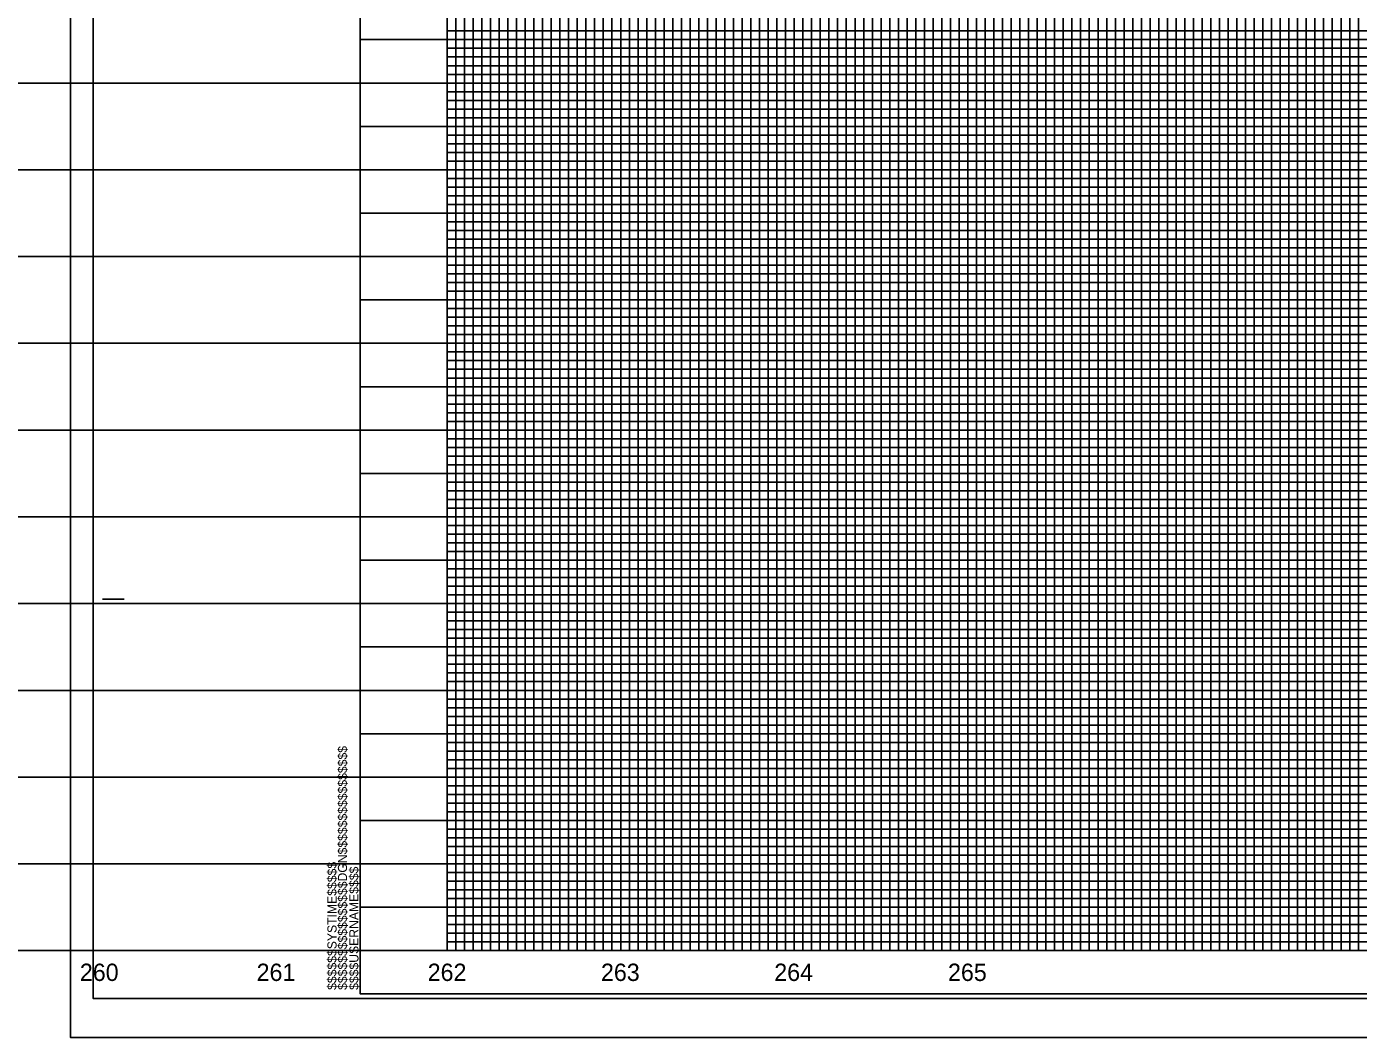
# Model space of a CAD drawing. Extents: x 2345490 to 2445302, y 465165 to 573888.
# Drawn here: x 2406279 to 2407047, y 564227 to 564809 of the extents above; entities that cross this region are included whole.
import ezdxf

# ---------------------------------------------------------------- set-up
doc = ezdxf.new("R2010")
doc.units = 0
for name, color, linetype in [('Old_Level_18', 7, 'Continuous'), ('Old_Level_40', 7, 'Continuous'), ('Old_Level_41', 7, 'Continuous'), ('Old_Level_42', 7, 'Continuous'), ('Old_Level_43', 7, 'Continuous'), ('Old_Level_50', 7, 'Continuous'), ('Old_Level_51', 7, 'Continuous'), ('Old_Level_52', 7, 'Continuous'), ('Old_Level_57', 7, 'Continuous'), ('Old_Level_62', 7, 'Continuous'), ('Old_Level_63', 7, 'Continuous')]:
    doc.layers.add(name, color=color, linetype=linetype)

msp = doc.modelspace()

# ---------------------------------------------------------------- linework, layer by layer
at = {"layer": 'Old_Level_18'}
msp.add_line((2406471.5425, 564251.534), (2406471.5425, 564251.534), dxfattribs=at)
msp.add_line((2406471.5425, 564251.534), (2406471.5425, 564251.534), dxfattribs=at)
msp.add_lwpolyline([(2407971.5425, 565301.534), (2406471.5425, 565301.534), (2406471.5425, 564251.534), (2407971.5425, 564251.534)], close=True, dxfattribs=at)
at = {"layer": 'Old_Level_40'}
msp.add_line((2406471.5425, 564251.534), (2406471.5425, 564251.534), dxfattribs=at)
msp.add_line((2406471.5425, 564251.534), (2406471.5425, 564251.534), dxfattribs=at)
msp.add_line((2406471.5425, 564251.534), (2406471.5425, 564251.534), dxfattribs=at)
msp.add_line((2406471.5425, 564251.534), (2406471.5425, 564251.534), dxfattribs=at)
at = {"layer": 'Old_Level_41'}
for p, q in [((2406323.0425, 564479.034), (2406335.5425, 564479.034)), ((2407971.5425, 564276.534), (2406471.5425, 564276.534))]:
    msp.add_line(p, q, dxfattribs=at)
for points in [[(2406471.5425, 565301.534), (2406521.5425, 565301.534), (2406521.5425, 564276.534), (2406571.5425, 564276.534), (2406571.5425, 565301.534), (2406621.5425, 565301.534), (2406621.5425, 564276.534), (2406671.5425, 564276.534), (2406671.5425, 565301.534), (2406721.5425, 565301.534), (2406721.5425, 564276.534), (2406771.5425, 564276.534), (2406771.5425, 565301.534), (2406821.5425, 565301.534), (2406821.5425, 564276.534), (2406871.5425, 564276.534), (2406871.5425, 565301.534), (2406921.5425, 565301.534), (2406921.5425, 564276.534), (2406971.5425, 564276.534), (2406971.5425, 565301.534), (2407021.5425, 565301.534), (2407021.5425, 564276.534), (2407071.5425, 564276.534)], [(2406546.5425, 564276.534), (2406546.5425, 565301.534), (2406596.5425, 565301.534), (2406596.5425, 564276.534), (2406646.5425, 564276.534), (2406646.5425, 565301.534), (2406696.5425, 565301.534), (2406696.5425, 564276.534), (2406746.5425, 564276.534), (2406746.5425, 565301.534), (2406796.5425, 565301.534), (2406796.5425, 564276.534), (2406846.5425, 564276.534), (2406846.5425, 565301.534), (2406896.5425, 565301.534), (2406896.5425, 564276.534), (2406946.5425, 564276.534), (2406946.5425, 565301.534), (2406996.5425, 565301.534), (2406996.5425, 564276.534), (2407046.5425, 564276.534), (2407046.5425, 565301.534), (2407096.5425, 565301.534)], [(2407971.5425, 564801.534), (2406471.5425, 564801.534), (2406471.5425, 564751.534), (2407971.5425, 564751.534)], [(2407971.5425, 564701.534), (2406471.5425, 564701.534), (2406471.5425, 564651.534), (2407971.5425, 564651.534)], [(2407971.5425, 564626.534), (2406471.5425, 564626.534), (2406471.5425, 564676.534), (2407971.5425, 564676.534)], [(2407971.5425, 564601.534), (2406471.5425, 564601.534), (2406471.5425, 564551.534), (2407971.5425, 564551.534)], [(2407971.5425, 564526.534), (2406471.5425, 564526.534), (2406471.5425, 564576.534), (2407971.5425, 564576.534)], [(2407971.5425, 564501.534), (2406471.5425, 564501.534), (2406471.5425, 564451.534), (2407971.5425, 564451.534)], [(2407971.5425, 564401.534), (2406471.5425, 564401.534), (2406471.5425, 564351.534), (2407971.5425, 564351.534)], [(2407971.5425, 564326.534), (2406471.5425, 564326.534), (2406471.5425, 564376.534), (2407971.5425, 564376.534)], [(2407971.5425, 564301.534), (2406471.5425, 564301.534)], [(2406509.0425, 564251.534), (2406509.0425, 564251.534)]]:
    msp.add_lwpolyline(points, dxfattribs=at)
at = {"layer": 'Old_Level_42'}
for points in [[(2407971.5425, 564726.534), (2406471.5425, 564726.534), (2406471.5425, 564776.534), (2407971.5425, 564776.534)], [(2407971.5425, 564426.534), (2406471.5425, 564426.534), (2406471.5425, 564476.534), (2407971.5425, 564476.534)]]:
    msp.add_lwpolyline(points, dxfattribs=at)
at = {"layer": 'Old_Level_43'}
for points in [[(2406526.5425, 565301.534), (2406526.5425, 564276.534), (2406531.5425, 564276.534), (2406531.5425, 565301.534)], [(2406536.5425, 565301.534), (2406536.5425, 564276.534), (2406541.5425, 564276.534), (2406541.5425, 565301.534)], [(2406551.5425, 565301.534), (2406551.5425, 564276.534), (2406556.5425, 564276.534), (2406556.5425, 565301.534)], [(2406561.5425, 565301.534), (2406561.5425, 564276.534), (2406566.5425, 564276.534), (2406566.5425, 565301.534)], [(2406576.5425, 565301.534), (2406576.5425, 564276.534), (2406581.5425, 564276.534), (2406581.5425, 565301.534)], [(2406586.5425, 565301.534), (2406586.5425, 564276.534), (2406591.5425, 564276.534), (2406591.5425, 565301.534)], [(2406601.5425, 565301.534), (2406601.5425, 564276.534), (2406606.5425, 564276.534), (2406606.5425, 565301.534)], [(2406611.5425, 565301.534), (2406611.5425, 564276.534), (2406616.5425, 564276.534), (2406616.5425, 565301.534)], [(2406626.5425, 565301.534), (2406626.5425, 564276.534), (2406631.5425, 564276.534), (2406631.5425, 565301.534)], [(2406636.5425, 565301.534), (2406636.5425, 564276.534), (2406641.5425, 564276.534), (2406641.5425, 565301.534)], [(2406651.5425, 565301.534), (2406651.5425, 564276.534), (2406656.5425, 564276.534), (2406656.5425, 565301.534)], [(2406661.5425, 565301.534), (2406661.5425, 564276.534), (2406666.5425, 564276.534), (2406666.5425, 565301.534)], [(2406676.5425, 565301.534), (2406676.5425, 564276.534), (2406681.5425, 564276.534), (2406681.5425, 565301.534)], [(2406686.5425, 564276.534), (2406691.5425, 564276.534), (2406691.5425, 565301.534)], [(2406686.5425, 565301.534), (2406686.5425, 564276.534)], [(2406701.5425, 565301.534), (2406701.5425, 564276.534), (2406706.5425, 564276.534), (2406706.5425, 565301.534)], [(2406711.5425, 565301.534), (2406711.5425, 564276.534), (2406716.5425, 564276.534), (2406716.5425, 565301.534)], [(2406726.5425, 565301.534), (2406726.5425, 564276.534), (2406731.5425, 564276.534), (2406731.5425, 565301.534)], [(2406736.5425, 565301.534), (2406736.5425, 564276.534), (2406741.5425, 564276.534), (2406741.5425, 565301.534)], [(2406751.5425, 565301.534), (2406751.5425, 564276.534), (2406756.5425, 564276.534), (2406756.5425, 565301.534)], [(2406761.5425, 565301.534), (2406761.5425, 564276.534), (2406766.5425, 564276.534), (2406766.5425, 565301.534)], [(2406776.5425, 565301.534), (2406776.5425, 564276.534), (2406781.5425, 564276.534), (2406781.5425, 565301.534)], [(2406786.5425, 565301.534), (2406786.5425, 564276.534), (2406791.5425, 564276.534), (2406791.5425, 565301.534)], [(2406801.5425, 565301.534), (2406801.5425, 564276.534), (2406806.5425, 564276.534), (2406806.5425, 565301.534)], [(2406811.5425, 565301.534), (2406811.5425, 564276.534), (2406816.5425, 564276.534), (2406816.5425, 565301.534)], [(2406826.5425, 565301.534), (2406826.5425, 564276.534), (2406831.5425, 564276.534), (2406831.5425, 565301.534)], [(2406836.5425, 565301.534), (2406836.5425, 564276.534), (2406841.5425, 564276.534), (2406841.5425, 565301.534)], [(2406851.5425, 565301.534), (2406851.5425, 564276.534), (2406866.5425, 564276.534), (2406866.5425, 565301.534)], [(2406856.5425, 565301.534), (2406856.5425, 564276.534), (2406861.5425, 564276.534), (2406861.5425, 565301.534)], [(2406856.5425, 565300.934), (2406856.5425, 564276.534), (2406861.5425, 564276.534), (2406861.5425, 565300.934)], [(2406876.5425, 565301.534), (2406876.5425, 564276.534), (2406881.5425, 564276.534), (2406881.5425, 565301.534)], [(2406886.5425, 565301.534), (2406886.5425, 564276.534), (2406891.5425, 564276.534), (2406891.5425, 565301.534)], [(2406901.5425, 565301.534), (2406901.5425, 564276.534), (2406906.5425, 564276.534), (2406906.5425, 565301.534)], [(2406911.5425, 565301.534), (2406911.5425, 564276.534), (2406916.5425, 564276.534), (2406916.5425, 565301.534)], [(2406926.5425, 565301.534), (2406926.5425, 564276.534), (2406931.5425, 564276.534), (2406931.5425, 565301.534)], [(2406936.5425, 565301.534), (2406936.5425, 564276.534), (2406941.5425, 564276.534), (2406941.5425, 565301.534)], [(2406951.5425, 565301.534), (2406951.5425, 564276.534), (2406956.5425, 564276.534), (2406956.5425, 565301.534)], [(2406961.5425, 565301.534), (2406961.5425, 564276.534), (2406966.5425, 564276.534), (2406966.5425, 565301.534)], [(2406976.5425, 565301.534), (2406976.5425, 564276.534), (2406981.5425, 564276.534), (2406981.5425, 565301.534)], [(2406986.5425, 565301.534), (2406986.5425, 564276.534), (2406991.5425, 564276.534), (2406991.5425, 565301.534)], [(2407001.5425, 565301.534), (2407001.5425, 564276.534)], [(2407006.5425, 565301.534), (2407006.5425, 564276.534), (2407011.5425, 564276.534), (2407011.5425, 565301.534), (2407016.5425, 565301.534), (2407016.5425, 564276.534), (2407026.5425, 564276.534), (2407026.5425, 565301.534), (2407031.5425, 565301.534), (2407031.5425, 564276.534), (2407036.5425, 564276.534), (2407036.5425, 565301.534), (2407041.5425, 565301.534), (2407041.5425, 564276.534)], [(2407921.5425, 564806.534), (2406521.5425, 564806.534), (2406521.5425, 564796.534), (2407921.5425, 564796.534)], [(2407921.5425, 564791.534), (2406521.5425, 564791.534), (2406521.5425, 564786.534), (2407921.5425, 564786.534)], [(2407921.5425, 564781.534), (2406521.5425, 564781.534)], [(2406521.5425, 564771.534), (2407921.5425, 564771.534)], [(2407921.5425, 564766.534), (2406521.5425, 564766.534), (2406521.5425, 564761.534), (2407921.5425, 564761.534)], [(2407921.5425, 564756.534), (2406521.5425, 564756.534), (2406521.5425, 564746.534), (2407921.5425, 564746.534)], [(2407921.5425, 564741.534), (2406521.5425, 564741.534), (2406521.5425, 564736.534), (2407921.5425, 564736.534)], [(2407921.5425, 564731.534), (2406521.5425, 564731.534), (2406521.5425, 564721.534), (2407921.5425, 564721.534)], [(2407921.5425, 564716.534), (2406521.5425, 564716.534), (2406521.5425, 564711.534), (2407921.5425, 564711.534)], [(2407921.5425, 564706.534), (2406521.5425, 564706.534), (2406521.5425, 564696.534), (2407921.5425, 564696.534)], [(2407921.5425, 564691.534), (2406521.5425, 564691.534), (2406521.5425, 564686.534), (2407921.5425, 564686.534)], [(2407921.5425, 564681.534), (2406521.5425, 564681.534), (2406521.5425, 564671.534), (2407921.5425, 564671.534)], [(2407921.5425, 564666.534), (2406521.5425, 564666.534), (2406521.5425, 564661.534), (2407921.5425, 564661.534)], [(2407921.5425, 564656.534), (2406521.5425, 564656.534), (2406521.5425, 564646.534), (2407921.5425, 564646.534)], [(2407921.5425, 564641.534), (2406521.5425, 564641.534), (2406521.5425, 564636.534), (2407921.5425, 564636.534)], [(2407921.5425, 564631.534), (2406521.5425, 564631.534), (2406521.5425, 564621.534), (2407921.5425, 564621.534)], [(2407921.5425, 564616.534), (2406521.5425, 564616.534), (2406521.5425, 564611.534), (2407921.5425, 564611.534)], [(2407921.5425, 564606.534), (2406521.5425, 564606.534), (2406521.5425, 564596.534), (2407921.5425, 564596.534)], [(2407921.5425, 564591.534), (2406521.5425, 564591.534), (2406521.5425, 564586.534), (2407921.5425, 564586.534)], [(2407921.5425, 564581.534), (2406521.5425, 564581.534), (2406521.5425, 564571.534), (2407921.5425, 564571.534)], [(2407921.5425, 564566.534), (2406521.5425, 564566.534), (2406521.5425, 564561.534), (2407921.5425, 564561.534)], [(2407921.5425, 564556.534), (2406521.5425, 564556.534), (2406521.5425, 564546.534), (2407921.5425, 564546.534)], [(2407921.5425, 564541.534), (2406521.5425, 564541.534), (2406521.5425, 564536.534), (2407921.5425, 564536.534)], [(2407921.5425, 564531.534), (2406521.5425, 564531.534), (2406521.5425, 564521.534), (2407921.5425, 564521.534)], [(2407921.5425, 564516.534), (2406521.5425, 564516.534), (2406521.5425, 564511.534), (2407921.5425, 564511.534)], [(2407921.5425, 564506.534), (2406521.5425, 564506.534), (2406521.5425, 564496.534), (2407921.5425, 564496.534)], [(2407921.5425, 564491.534), (2406521.5425, 564491.534), (2406521.5425, 564486.534), (2407921.5425, 564486.534)], [(2407921.5425, 564481.534), (2406521.5425, 564481.534)], [(2406521.5425, 564471.534), (2407921.5425, 564471.534)], [(2407921.5425, 564466.534), (2406521.5425, 564466.534), (2406521.5425, 564461.534), (2407921.5425, 564461.534)], [(2407921.5425, 564456.534), (2406521.5425, 564456.534)], [(2406521.5425, 564446.534), (2407921.5425, 564446.534)], [(2407921.5425, 564441.534), (2406521.5425, 564441.534), (2406521.5425, 564436.534), (2407921.5425, 564436.534)], [(2407921.5425, 564431.534), (2406521.5425, 564431.534), (2406521.5425, 564421.534), (2407921.5425, 564421.534)], [(2407921.5425, 564416.534), (2406521.5425, 564416.534), (2406521.5425, 564411.534), (2407921.5425, 564411.534)], [(2407921.5425, 564406.534), (2406521.5425, 564406.534), (2406521.5425, 564396.534), (2407921.5425, 564396.534)], [(2407921.5425, 564391.534), (2406521.5425, 564391.534), (2406521.5425, 564386.534), (2407921.5425, 564386.534)], [(2407921.5425, 564381.534), (2406521.5425, 564381.534), (2406521.5425, 564371.534), (2407921.5425, 564371.534)], [(2407921.5425, 564366.534), (2406521.5425, 564366.534), (2406521.5425, 564361.534), (2407921.5425, 564361.534)], [(2407921.5425, 564356.534), (2406521.5425, 564356.534), (2406521.5425, 564346.534), (2407921.5425, 564346.534)], [(2407921.5425, 564341.534), (2406521.5425, 564341.534), (2406521.5425, 564336.534), (2407921.5425, 564336.534)], [(2407921.5425, 564331.534), (2406521.5425, 564331.534), (2406521.5425, 564321.534), (2407921.5425, 564321.534)], [(2407921.5425, 564316.534), (2406521.5425, 564316.534), (2406521.5425, 564311.534), (2407921.5425, 564311.534)], [(2407921.5425, 564306.534), (2406521.5425, 564306.534), (2406521.5425, 564296.534), (2407921.5425, 564296.534)], [(2407921.5425, 564291.534), (2406521.5425, 564291.534), (2406521.5425, 564286.534), (2407921.5425, 564286.534)], [(2407921.5425, 564281.534), (2406521.5425, 564281.534)]]:
    msp.add_lwpolyline(points, dxfattribs=at)
at = {"layer": 'Old_Level_50'}
msp.add_line((2406304.5425, 564226.534), (2406304.5425, 564226.534), dxfattribs=at)
msp.add_lwpolyline([(2407984.0425, 565304.084), (2406317.5425, 565304.084), (2406317.5425, 564248.984), (2407984.0425, 564248.984)], close=True, dxfattribs=at)
at = {"layer": 'Old_Level_51'}
msp.add_lwpolyline([(2407988.5425, 565326.534), (2406304.5425, 565326.534), (2406304.5425, 564226.534), (2407988.5425, 564226.534)], close=True, dxfattribs=at)
at = {"layer": 'Old_Level_52'}
msp.add_line((2406317.5425, 564248.984), (2406317.5425, 564248.984), dxfattribs=at)
at = {"layer": 'Old_Level_57'}
for p, q in [((2381271.54275, 564776.534), (2410861.123, 564776.534)), ((2381271.5425, 564726.534), (2410861.12275, 564726.534)), ((2381271.54275, 564676.534), (2410861.123, 564676.534)), ((2381271.5425, 564626.534), (2410861.12275, 564626.534)), ((2381271.54275, 564576.534), (2410861.123, 564576.534)), ((2381271.5425, 564526.534), (2410861.12275, 564526.534)), ((2381271.54275, 564476.534), (2410861.123, 564476.534)), ((2381271.5425, 564426.534), (2410861.12275, 564426.534)), ((2381271.54275, 564376.534), (2410861.123, 564376.534)), ((2381271.5425, 564326.534), (2410861.12275, 564326.534)), ((2381271.54275, 564276.534), (2410861.123, 564276.534))]:
    msp.add_line(p, q, dxfattribs=at)
at = {"layer": 'Old_Level_63'}
msp.add_line((2381321.5425, 564276.534), (2406689.937, 564276.534), dxfattribs=at)

# ---------------------------------------------------------------- texts
at = {"layer": 'Old_Level_41'}
for s, p in [('$$$$$$$$$$$$$$$$DGN$$$$$$$$$$$$$$$$', (2406463.8925, 564253.8965)), ('$$$$$$SYSTIME$$$$$', (2406457.8425, 564253.8965)), ('$$$$USERNAME$$$$', (2406470.4675, 564253.909))]:
    msp.add_text(s, height=5.25, rotation=90, dxfattribs=at).set_placement(p)
at = {"layer": 'Old_Level_62'}
for s, p in [('260', (2406309.9745, 564259.034)), ('261', (2406411.814, 564259.034)), ('262', (2406510.36225, 564259.034)), ('263', (2406610.197, 564259.034)), ('264', (2406710.0395, 564259.034)), ('265', (2406810.132, 564259.034))]:
    msp.add_text(s, height=10.000001, dxfattribs=at).set_placement(p)

doc.saveas('drawing.dxf')
